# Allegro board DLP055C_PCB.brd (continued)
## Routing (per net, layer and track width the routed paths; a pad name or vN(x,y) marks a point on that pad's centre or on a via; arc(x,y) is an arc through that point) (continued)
UART0_TXD_CON: length 20.6
  TOP w0.191: U46.7 18.82,33.36 16.63,33.36 15.67,32.39 15.67,29.22 14.7,28.25 9.78,28.25 9.37,28.66 J102.2
UART0_VP: length 2.8
  TOP w0.191: U46.2 21.51,30.12 C692.1
UART1_CTSZ: length 92.6
  TOP w0.191: U15.R1 150.95,73.51 150.97,73.48 150.97,73.2 150.97,72.91 149.7,71.64 149.5,71.64 149.12,71.27 149.12,71.22 149.09,71.18 149.09,68.01 149.01,67.93 149.01,67.91 146.14,65.05 146.14,61.2 146.13,61.19 146.13,60.73 146.14,60.72 146.14,58.89 150.36,54.67 150.57,54.67 152.8,52.43 152.8,49.16 153.46,48.5 167.59,48.5 168.93,47.15 168.93,43.95 v1(169.44,43.44)
  LY5 w0.122: v1(169.44,43.44) 172.11,40.78 172.11,28.05 169.41,25.36 167.94,25.36 167.33,24.75 J105.2
  LY12 w0.122: J105.2 167.33,21.32 169.23,19.42 169.23,13.4 170.68,11.95 170.68,9.08 169.46,7.86
UART1_RTSZ: length 92.9
  TOP w0.102: 150.29,73.34 150.29,73.48 150.36,73.56 150.36,75.17 150.6,75.4 U15.R2
  TOP w0.191: v1(144.24,62.57) 145.04,63.37 145.04,64.92 148.32,68.2 148.32,68.21 148.4,68.29 148.4,71.41 148.37,71.44 148.38,71.45 148.44,71.51 148.44,71.55 149.21,72.33 149.42,72.33 150.29,73.2 150.29,73.34
  LY3 w0.122: 161.34,23.1 161.34,24.06 161.03,24.37 161.03,30.59 159.94,31.68 159.94,39.96 159.51,40.39 156.08,40.39 152.95,37.27 149.09,37.27 148.56,37.8 148.56,38.85 v1(148.54,38.87)
  LY12 w0.122: J113.5 163.24,14.08 163.24,18.17 161.34,20.07 161.34,23.1 ; v1(144.24,62.57) 144.1,62.57 141.12,59.59 141.12,57.06 141.42,56.75 141.42,53.14 141.11,52.83 141.11,52.66 141.09,52.64 141.09,48.96 141.11,48.94 141.11,43.7 142.98,41.84 142.98,41.13 143.6,40.51 145.77,40.51 146.45,39.84 147.57,39.84 v1(148.54,38.87)
UART1_RXD: length 96
  TOP w0.102: 150.63,73.34 150.63,74.18 150.57,74.24 150.57,74.56 150.82,74.81 151.28,74.81 151.43,74.96 151.43,75.8 151.95,76.32 U15.T3
  TOP w0.191: 150.63,73.34 150.63,73.05 149.56,71.98 149.36,71.98 148.78,71.41 148.78,71.36 148.74,71.32 148.74,68.15 148.66,68.07 148.66,68.06 145.39,64.78 v1(145.39,62.62)
  LY3 w0.122: v1(149.58,38.06) 152.9,38.06 155.6,40.75 159.97,40.75 160.6,40.12 160.6,31.89 161.44,31.05 161.44,24.49 J105.5
  LY12 w0.122: J105.5 165.07,20.86 165.07,14.03 167.38,11.72 168.14,11.72 J113.3 ; v1(145.39,62.62) 143.51,60.74 142.67,60.74 141.4,59.47 141.4,57.17 141.7,56.87 141.7,53.02 141.39,52.71 141.39,52.55 141.37,52.53 141.37,49.08 141.39,49.06 141.39,44.11 143.25,42.25 143.25,41.24 143.71,40.79 145.89,40.79 146.56,40.12 148.48,40.12 149.58,39.02 v1(149.58,38.06)
UART1_TXD: length 106.6
  TOP w0.191: U15.T4 v1(151.45,77.9)
  LY3 w0.122: v1(153.74,39.99) 154.86,41.11 160.27,41.11 161.08,40.29 161.08,31.96 161.79,31.25 161.79,25.64 J105.4
  LY12 w0.122: J105.4 166.24,25 169.64,25 171.95,22.69 171.95,17.87 169.82,15.73 169.82,13.83 171.04,12.61 172.74,12.61 173.58,11.77 173.58,9.41 172.03,7.86 172,7.86 ; v1(153.74,39.99) 152.37,41.36 151.91,41.36 151.68,41.59 151.68,45.09 150.34,46.44 148.87,46.44 147.42,47.89 144.38,47.89 142.76,49.51 142.76,49.63 142.74,49.65 142.74,51.96 142.76,51.98 142.76,52.1 143.25,52.6 143.25,55.73 145.54,58.02 145.54,58.75 145.54,58.75 145.54,58.79 145.57,58.81 145.57,58.95 147.81,61.2 148.72,61.2 149.05,61.53 149.09,61.53 150.24,62.68 150.24,62.72 150.44,62.92 150.44,64.07 151.33,64.96 151.33,67.27 150.14,68.46 150.14,72.73 150.75,73.34 150.75,74.89 151.96,76.11 151.96,77.35 151.45,77.87 v1(151.45,77.9)
UART2_RXD: length 75.9
  TOP w0.191: J103.5 95.92,137.91 J111.3
  LY12 w0.122: J103.5 95.92,132.44 J98.2
  BOTTOM w0.191: J98.2 96.7,129.68 111.35,129.68 124.05,116.98 124.05,108.57 128.88,103.74 133.12,103.74 134.41,105.04 134.41,106.74 135.43,107.76 139.46,107.76 R615.1
UART2_TXD: length 160.4
  TOP w0.191: v1(171.98,107.99) 170.23,109.74 167.14,109.74 163.75,113.13 160.47,113.13 158.36,115.24 158.36,120.47 155.96,122.87 152.58,122.87 146.56,116.85 146.56,114.7 145.61,113.75 144.17,113.75 143.3,112.88 140.97,112.88 140.65,112.57 v1(140.65,111.82) R614.1 ; J103.4 97.42,144.42 95.78,146.06 92.4,146.06 J111.2
  LY12 w0.122: v1(171.98,107.99) 175.69,104.28 175.69,93.43 173.02,90.76 173.02,88.9 172.13,88.01 172.13,85.62 171.73,85.22 171.73,76.11 v1(169.67,74.05)
  BOTTOM w0.191: v1(169.67,74.05) 171.65,72.06 R711.1 ; v1(140.65,111.82) 140.65,112.32 140.65,112.33 140.63,112.33 140.1,112.86 131.58,112.86 128.99,115.45 126.51,115.45 109.5,132.46 109.5,132.5 109.32,132.67 104.06,132.67 103.07,133.66 99.65,133.66 J103.4
USB_AUX: length 1.8
  TOP w0.191: U7.10 86.46,127.54 v1(85.97,128.04)
  BOTTOM w0.191: v1(85.97,128.04) 85.97,127.87 R91.1
USB_DAT_N: length 80.4
  TOP w0.152: v1(81.79,139.55) 82.08,139.84 82.08,140.13 R4.1
  TOP w0.191: U15.A27 v1(136.45,100.9)
  LY3 w0.076: 136.86,101.31 136.86,102.13 136.68,102.31 136.07,102.31 136.04,102.29 135.93,102.29
  LY3 w0.102: 135.93,102.29 135.9,102.26 135.88,102.26 ; v1(136.45,100.9) 136.86,101.31
  LY3 w0.127: 135.88,102.26 135.52,102.26 135.13,102.66 134.94,102.66 134.93,102.65
  LY3 w0.132: 134.93,102.65 131.53,102.65 127.4,106.78 113.99,106.78 105.94,114.84 101.58,114.84 101.58,114.84 101.47,114.84 94.94,121.37 88.81,121.37 82.09,128.09 82.09,139.25 v1(81.79,139.55)
USB_DAT_N_IN: length 6.3
  TOP w0.152: J2.2 81.9,146.39 82.07,146.22 82.07,143.53 U1.5 82.01,142.55 82.01,142.34 81.76,142.09 R4.2
USB_DAT_P: length 80.5
  TOP w0.152: R5.1 82.38,140.13 82.38,139.83 v1(82.66,139.55)
  TOP w0.191: U15.B27 v1(137.45,100.9)
  LY3 w0.076: 135.96,102.49 135.99,102.49 136.75,102.49 137.03,102.2 137.03,101.4 137.05,101.39 137.05,101.24 137.01,101.2 137.01,101.18 137,101.17 137,101
  LY3 w0.102: 137,101 137.1,100.9 v1(137.45,100.9) ; 135.88,102.54 135.9,102.54 135.96,102.49
  LY3 w0.127: 135.88,102.54 135.63,102.54 135.24,102.93 135.05,102.93 134.93,102.93
  LY3 w0.132: v1(82.66,139.55) 82.37,139.25 82.37,128.2 88.92,121.65 95.06,121.65 101.59,115.12 106.05,115.12 114.11,107.06 127.51,107.06 131.64,102.93 134.93,102.93
USB_DAT_P_IN: length 6.5
  TOP w0.152: 82.62,144.01 82.61,144.01 82.38,143.78 82.38,143.31 82.31,143.25 82.31,141.89 R5.2 ; 82.62,144.01 82.38,144.25 82.38,146.22 82.55,146.39 J2.3 ; 82.62,144.01 U1.3
USB_EN: length 6.3
  TOP w0.191: U7.4 87.96,123.99 88.47,123.48 88.47,119.41 R13.1 R14.1
USB_ENUSB: length 1.3
  TOP w0.191: R8.1 88.26,128.39 87.96,128.09 U7.7
USB_FAULTZ: length 8
  TOP w0.191: U7.8 87.46,128.31 v1(87.55,128.4)
  LY12 w0.122: TP9.1 83.96,131.36 86.93,128.4 v1(87.55,128.4)
  BOTTOM w0.191: v1(87.55,128.4) 87.46,128.31 87.46,127.41 R91.2
USB_ID: length 85
  TOP w0.191: J2.4 83.2,145.49 83.85,144.84 TP286.1 ; U15.C27 v1(138.45,100.9)
  LY3 w0.122: v1(138.45,100.9) 138.45,101.57 137.21,102.81 137.21,102.85 136.65,103.41 136.24,103.41 135.68,103.97 131.75,103.97 126.75,108.97 114.76,108.97 107.76,115.97 103.16,115.97 99.08,120.05 99.08,124.7 98.2,125.58 v1(94.7,125.58)
  LY12 w0.122: v1(94.7,125.58) 93.83,126.45 93.83,130.26 90.62,133.46 90.62,138.18 88.03,140.78 88.03,142.05 TP286.1
USB_ILIM: length 1.5
  TOP w0.191: R11.1 89.21,127.41 89.09,127.29 U7.6
USB_OTG_CP_EN: length 97.7
  TOP w0.191: U15.AB26 v1(158.45,99.9) ; R8.2 v1(90.35,128.39) ; R14.2 v1(91.23,119.39)
  LY3 w0.076: 142.99,99.14 142.82,99.31 139.62,99.31 137.17,99.31
  LY3 w0.102: 137.17,99.31 136.72,98.87 135.88,98.87 ; v1(158.45,99.9) 158.45,99.89 157.94,99.38 157.21,99.38 157.01,99.18 157.01,98.67 156.76,98.43 143.13,98.43 142.99,98.57 142.99,99.14
  LY3 w0.122: v1(91.51,106.1) 91.82,105.8 92.33,105.8 98.98,99.15 120.52,99.15 120.9,98.76 123.9,98.76 124.08,98.94 133.78,98.94 134.24,99.4 135.18,99.4 135.72,98.87 135.88,98.87
  LY12 w0.122: v1(91.51,106.1) 91.19,106.43 91.19,119.36 v1(91.23,119.39) 90.06,120.56 90.06,128.1 v1(90.35,128.39)
USB_TXRTUNE: length 2
  TOP w0.191: U15.C26 v1(139.45,98.9)
  BOTTOM w0.191: v1(139.45,98.9) 138.97,99.38 R114.2
USB_VBUS: length 85.8
  TOP w0.191: 85.84,130.89 v1(85.84,130.89) C7.2 86.96,130.89 ; U15.D26 v1(139.45,99.9)
  TOP w0.381: J2.1 81.25,145.83 v1(81.24,145.82)
  LY12 w0.635: v1(81.24,145.82) 85.84,141.22 v1(85.84,139.02)
  BOTTOM w0.381: v1(139.45,99.9) 139.36,99.9 139.08,100.18 134.32,100.18
  BOTTOM w0.635: 134.32,100.18 133.67,99.53 126.79,99.53 120.7,105.62 120.7,117.34 109.83,128.2 101.6,128.2 100.86,128.94 93.59,128.94 93.29,129.25 87.48,129.25 v1(85.84,130.89)
  vias: v1(85.84,138) v1(85.84,136.99) v1(85.84,135.97) v1(85.84,134.95) v1(85.84,133.94) v1(85.84,132.92) v1(85.84,131.91)
USBDM: length 11.8
  TOP w0.152: U562.15 21.74,76.86 21.5,76.62 20.87,76.62 20.7,76.44 20.7,76.08 20.47,75.85 19.58,75.85 19.15,76.29 18.74,76.29 U501.5 18.69,76.34 18,76.34 16.99,77.35 16.71,77.35 15.31,78.75 14.33,78.75 14.07,78.49 14.07,78.28 J83.2
USBDP: length 11.7
  TOP w0.152: J83.3 13.77,78.28 13.77,78.62 14.2,79.05 15.44,79.05 16.84,77.66 17.52,77.66 17.73,77.87 19.01,77.87 19.53,77.35 20.03,77.35 U501.3 20.46,77.34 20.87,76.92 21.37,76.92 21.8,77.36 U562.14
UVLO_PWRDWN_1: length 63.7
  TOP w0.191: R886.1 v1(88.36,94.55)
  LY5 w0.122: v1(88.36,94.55) 87.37,94.55 85.85,96.07 85.85,104.07 78.81,111.11 78.81,114.97 71.9,121.88 71.9,138.72 74.01,140.83 74.01,145.32 v1(75.31,146.62)
  BOTTOM w0.191: v1(75.31,146.62) 76.2,145.72 U520.4
UVLO_PWRDWN_2: length 73.2
  TOP w0.191: R887.1 v1(81.54,88.76)
  LY5 w0.122: v1(81.54,88.76) 81.22,88.76 79.5,90.48 79.5,103.39 77.16,105.72 74.82,105.72 63.55,117 v1(63.55,149.77)
  BOTTOM w0.191: v1(63.55,149.77) 64.13,149.77 64.55,149.35 U568.4
VAD18_PLLMA: length 3.4
  TOP w0.191: U15.AE19 v1(161.45,92.9)
  BOTTOM w0.381: L15.1 C183.1 U15.AE19 v1(161.45,92.9)
VAD18_PLLMB: length 3.1
  TOP w0.191: U15.F14 v1(141.45,86.9)
  BOTTOM w0.381: C227.1 v1(141.45,86.9) L23.1 C225.1
VAD18_VX1: length 11.2
  TOP w0.191: U15.L19 v1(146.45,92.9) ; U15.E18 v1(140.45,91.9)
  LY3 w0.381: v1(146.45,92.9) 144.91,92.9 144.67,93.14 143.6,93.14 143.14,93.6 142.33,93.6 141.37,92.64 141.19,92.64 v1(140.45,91.9)
  BOTTOM w0.381: v1(146.45,92.9) U15.L19 ; C205.1 v1(140.45,91.9) ; v1(140.45,91.9) C204.1 ; v1(140.45,91.9) U15.E18
VAD33_OSCA: length 2.1
  TOP w0.191: U15.Y18 v1(156.45,91.9)
  BOTTOM w0.381: L17.1 v1(156.45,91.9) U15.Y18
VAD33_OSCB: length 2.1
  TOP w0.191: U15.L17 v1(146.45,90.9)
  BOTTOM w0.381: L20.1 v1(146.45,90.9) U15.L17
VAD33_USB: length 8.3
  TOP w0.191: U15.F25 v1(141.45,98.9) ; U15.D27 v1(139.45,100.9) ; U15.E26 v1(140.45,99.9)
  BOTTOM w0.381: C152.2 v1(139.45,100.9) v1(140.45,99.9) U15.E26 v1(141.45,98.9) U15.F25 143.11,97.03 C172.2
VAD115_VX1: length 12.3
  TOP w0.191: U15.F24 v1(141.45,97.9) ; U15.L18 v1(146.45,91.9)
  LY12 w0.381: v1(141.45,97.9) 145.22,94.12 145.22,93.12 v1(146.45,91.9)
  BOTTOM w0.381: v1(146.45,91.9) U15.L18 ; v1(146.45,91.9) C200.1 ; v1(146.45,91.9) L18.1 ; v1(141.45,97.9) C174.1
VBIAS_MON: length 27.8
  TOP w0.191: v1(158.19,69.12) 158,68.93 R235.1 ; TP285.1 179.12,74.6 179.36,74.6 179.37,74.6 179.4,74.6 179.4,74.59 179.83,74.59 179.84,74.6 179.88,74.6 179.88,74.6 J10.47
  LY3 w0.122: v1(158.19,69.12) 158.26,69.2 159.94,69.2 161.69,70.95 162.05,70.95 163.95,72.86 166.06,72.86 167.69,71.23 169.08,71.23 172.23,74.38 177.62,74.38 TP285.1
VUSB: length 10.5
  TOP w0.191: TP77.1 38.07,108.3 38.07,110.27 34.39,113.95 U26.66
VX1_CM_AMOUT0: length 27.8
  TOP w0.191: U15.F19 141.95,92.4 142.19,92.16 v1(142.69,92.16)
  LY3 w0.076: 141.63,87.31 141.62,87.31 141.62,87.31 141.28,87.31 141.27,87.31 140.62,87.31 140.62,87.31 140.28,87.31 140.27,87.31 139.62,87.31 139.62,87.31 139.28,87.31 139.27,87.31 138.62,87.31 138.62,87.31 138.28,87.31 138.27,87.31 137.62,87.31 137.62,87.31 137.28,87.31 137.27,87.31 136.62,87.31 136.62,87.31 136.28,87.31 136.27,87.31 136.08,87.31 135.88,87.51
  LY3 w0.102: v1(142.69,92.16) 142.24,92.16 142.06,91.98 142.06,87.74 141.63,87.31
  LY3 w0.122: TP106.1 122.12,87.11 128.77,87.11 129.17,87.51 135.88,87.51
VX1_CM_AMOUT1: length 28.3
  TOP w0.102: U15.F21 v1(141.45,94.9)
  LY3 w0.076: 139.95,95.1 140.17,95.31 140.2,95.31 141.03,95.31 v1(141.45,94.9)
  LY3 w0.102: 139.95,95.1 139.95,94.66 139.59,94.3 138.24,94.3 137.85,94.69 135.88,94.69
  LY3 w0.122: 135.88,94.69 135.84,94.65 129.39,94.65 128.96,95.08 117.5,95.08 117.03,94.61 TP107.1
VX1_CM_AMOUT2: length 31.4
  TOP w0.102: U15.F22 v1(141.45,95.9)
  LY3 w0.076: v1(141.45,95.9) 141.04,96.3 140.63,96.3 140.62,96.31 140.28,96.31 140.27,96.3 135.98,96.3
  LY3 w0.102: 135.98,96.3 135.88,96.2
  LY3 w0.122: 135.88,96.2 132.91,96.2 131.95,97.16 129.86,97.16 129,96.3 117.87,96.3 117.01,97.16 TP108.1
VX1_CM_AMOUT3: length 25.9
  TOP w0.102: U15.F23 v1(141.45,96.9)
  LY3 w0.076: 137.84,97.31 138.27,97.31 138.28,97.31 138.62,97.31 138.62,97.31 139.27,97.31 139.28,97.31 139.62,97.31 139.62,97.31 140.27,97.31 140.28,97.31 140.62,97.31 140.62,97.31 141.02,97.31 141.43,96.9 v1(141.45,96.9)
  LY3 w0.102: 135.88,97.11 137.64,97.11 137.84,97.31
  LY3 w0.122: v1(125.35,97.27) 125.83,97.75 135.1,97.75 135.73,97.11 135.88,97.11
  LY12 w0.122: v1(125.35,97.27) 125.35,103.54 124.78,104.11 TP109.1
VX1_DATA0_N: length 9.4
  TOP w0.102: U15.D18 139.65,91.4 139.55,91.5 139.55,91.73 139.26,92.02 135.95,92.02 135.9,92.07 135.88,92.07
  TOP w0.127: 135.88,92.07 135.79,92.07 135.48,91.76 135.48,90.42 133.95,88.89 133.56,88.89 C72.1
VX1_DATA0_P: length 9
  TOP w0.102: 135.88,91.73 135.97,91.82 139.17,91.82 139.35,91.65 139.35,91.5 139.24,91.4 U15.C18
  TOP w0.127: C73.1 133.56,88.59 134.08,88.59 135.79,90.3 135.79,91.64 135.88,91.73
VX1_DATA1_N: length 6.6
  TOP w0.102: U15.B19 137.65,92.4 137.55,92.5 137.55,92.73 137.28,93 136.53,93 136.53,92.99 136.44,92.99 136.4,92.99 136.38,92.97 135.98,92.97 135.9,93.05 135.88,93.05
  TOP w0.127: 135.88,93.05 135.62,93.05 134.62,92.05 134.62,91.44 133.97,90.8 133.56,90.8 C67.1
VX1_DATA1_P: length 6.2
  TOP w0.102: 135.88,92.74 136,92.74 136.03,92.77 136.1,92.77 136.46,92.77 136.48,92.79 136.61,92.79 136.62,92.8 137.19,92.8 137.35,92.64 137.35,92.5 137.24,92.4 U15.A19
  TOP w0.127: C68.1 133.56,90.49 134.1,90.49 134.92,91.32 134.92,91.92 135.74,92.74 135.88,92.74
VX1_DATA2_N: length 7.8
  TOP w0.102: 135.88,94.07 136,94.07 136.04,94.03 136.3,94.03 136.46,94.03 136.48,94.01 139.26,94.01 139.55,93.73 139.55,93.5 139.65,93.4 U15.D20
  TOP w0.127: 135.88,94.07 135.5,94.07 134.14,92.7 133.56,92.7 C65.1
VX1_DATA2_P: length 7.5
  TOP w0.102: 135.88,93.76 135.89,93.76 135.9,93.77 135.9,93.78 135.96,93.83 136.38,93.83 136.4,93.81 139.18,93.81 139.35,93.65 139.35,93.5 139.24,93.4 U15.C20
  TOP w0.127: C66.1 133.56,92.4 134.27,92.4 135.63,93.76 135.88,93.76
VX1_DATA3_N: length 5.4
  TOP w0.102: 135.88,95.03 135.9,95.03 135.96,94.97 136.04,94.97 136.4,94.97 136.41,94.98 136.7,94.98 136.71,94.98 137.19,94.98 137.19,94.98 137.3,94.98 137.55,94.73 137.55,94.5 137.65,94.4 U15.B21
  TOP w0.127: 135.88,95.03 135.15,95.03 134.73,94.61 133.56,94.61 C63.1
VX1_DATA3_P: length 5.1
  TOP w0.102: 135.88,94.73 136,94.73 136.05,94.77 136.12,94.77 136.48,94.77 136.49,94.78 136.78,94.78 136.79,94.78 137.11,94.78 137.11,94.78 137.22,94.78 137.35,94.65 137.35,94.5 137.24,94.4 U15.A21
  TOP w0.127: C64.1 133.56,94.3 134.85,94.3 135.28,94.73 135.88,94.73
VX1_DATA4_N: length 7.4
  TOP w0.102: 135.88,96.06 136,96.06 136.04,96.03 136.12,96.03 136.48,96.03 136.5,96.01 139.27,96.01 139.55,95.73 139.55,95.5 139.65,95.4 U15.D22
  TOP w0.127: 135.88,96.06 135.2,96.06 134.75,96.51 133.56,96.51 C61.1
VX1_DATA4_P: length 7.1
  TOP w0.102: U15.C22 139.24,95.4 139.35,95.5 139.35,95.65 139.18,95.81 136.42,95.81 136.4,95.83 135.95,95.83 135.9,95.78 135.9,95.77 135.89,95.76 135.88,95.76
  TOP w0.127: C62.1 133.56,96.21 134.62,96.21 135.07,95.76 135.88,95.76
VX1_DATA5_N: length 5.8
  TOP w0.102: 135.88,97.07 135.9,97.07 135.95,97.02 137.26,97.02 137.55,96.73 137.55,96.5 137.65,96.4 U15.B23
  TOP w0.127: 135.88,97.07 135.48,97.07 134.13,98.42 133.56,98.42 C53.1
VX1_DATA5_P: length 5.5
  TOP w0.102: U15.A23 137.24,96.4 137.35,96.5 137.35,96.65 137.18,96.82 135.95,96.82 135.9,96.77 135.88,96.77
  TOP w0.127: C54.1 133.56,98.11 134.01,98.11 135.36,96.77 135.88,96.77
VX1_DATA6_N: length 9.9
  TOP w0.102: U15.D24 139.65,97.4 139.55,97.5 139.55,97.73 139.26,98.02 138.79,98.02 138.57,98.24 138.57,99.75 138.3,100.02 136.47,100.02 136.45,100.04 136.29,100.04 136.17,100.04 136.17,100.06 136.11,100.12 136.11,100.14 135.93,100.32 135.88,100.32
  TOP w0.127: 135.88,100.32 135.78,100.32 133.87,102.23 133.56,102.23 C49.1
VX1_DATA6_P: length 9.5
  TOP w0.102: U15.C24 139.24,97.4 139.35,97.5 139.35,97.65 139.18,97.82 138.71,97.82 138.36,98.16 138.36,99.66 138.21,99.82 136.39,99.82 136.37,99.84 136.09,99.84 135.97,99.96 135.97,99.98 135.94,100.01 135.88,100.01
  TOP w0.127: C50.1 133.56,101.92 133.74,101.92 135.66,100.01 135.88,100.01
VX1_DATA7_N: length 5.8
  TOP w0.102: U15.B25 137.65,98.4 137.55,98.5 137.55,98.73 137.28,98.99 136.38,98.99 136.37,98.98 135.96,98.98 135.89,99.04 135.88,99.04
  TOP w0.127: 135.88,99.04 135.52,99.04 134.24,100.32 133.56,100.32 C51.1
VX1_DATA7_P: length 5.4
  TOP w0.102: U15.A25 137.24,98.4 137.35,98.5 137.35,98.65 137.2,98.79 136.46,98.79 136.45,98.78 136.29,98.78 136.04,98.78 136,98.74 135.88,98.74
  TOP w0.127: 135.88,98.74 135.4,98.74 134.12,100.02 133.56,100.02 C52.1
VX1_PROJ_ON: length 19.6
  TOP w0.191: J3.22 119.16,142.78 v1(119.16,142.78)
  LY3 w0.122: J68.2 114.21,140.34 114.85,140.98 116.91,140.98 118.33,142.4 118.35,142.4 118.62,142.67 118.62,142.69 118.71,142.77 119.15,142.77 119.16,142.78 v1(119.16,142.78)
WRP_CAMERA_TRIG: length 27.3
  TOP w0.191: J503.3 152.76,55.38 155.57,55.38 156.88,56.69 156.88,58.52 155.29,60.1 155.29,63.74 154.63,64.4 152.82,64.4 151.63,65.59 151.63,66.49 152.27,67.13 152.3,67.13 152.68,67.5 154.08,67.5 154.09,67.51 154.14,67.51 154.97,68.35 154.97,68.63 154.97,68.63 154.97,70.12 155.26,70.41 155.55,70.41 R675.1
N30083522: length 9.9
  TOP w0.191: U15.AC28 v1(159.45,101.9) ; R673.2 163.65,107.43 163.47,107.25 v1(163.47,105.32)
  LY3 w0.122: v1(159.45,101.9) 159.45,101.9 159.99,102.45 161.84,102.45 161.97,102.57 161.97,104.32 162.96,105.32 v1(163.47,105.32)
N30083525: length 10.6
  TOP w0.191: U15.AC26 v1(159.45,99.9)
  BOTTOM w0.191: v1(159.45,99.9) 159.45,99.95 159.91,100.42 162.76,100.42 163.01,100.67 163.01,101.61 163.95,102.55 163.95,104.83 164.15,105.03 R672.2
N30120583: length 1.4
  BOTTOM w0.381: R739.1 v1(79.23,55.43)
N30120605: length 10
  TOP w0.191: C752.1 65.32,46.99 65.32,48.11 65.76,48.55 66.6,48.55 68.6,50.54 68.6,51.88 68.99,52.27 68.99,52.82 69.04,52.87 69.04,53.57 68.88,53.73 U555.21
N30120666: length 5
  TOP w0.191: U555.17 66.88,53.61 66.68,53.4 66.68,52.74 64.58,50.64 C756.2
N30120670: length 4.8
  TOP w0.191: C756.1 66.26,51.45 67.4,52.6 67.4,52.6 67.7,52.89 67.7,52.98 67.69,52.99 67.69,53.31 67.67,53.33 67.67,53.33 67.4,53.6 67.38,53.6 67.38,53.61 U555.18
N30120771: length 18.4
  BOTTOM w1.016: R742.2 74.85,55.28 82.42,47.71 v1(82.42,42.53) v1(83.84,41.11)
N30120877: length 6.3
  TOP w0.191: TP228.1 74.45,58.69 73.25,58.69 73.14,58.8 U555.30
  BOTTOM w0.889: R742.1 74.77,57.57 TP228.1 75.05,59.29 R747.2
N30121099: length 0.9
  TOP w0.203: 72.99,60.31 U555.33
N30121105: length 4.2
  BOTTOM w0.381: v1(79.17,59.67) 79.17,60.69 78.53,61.32 76.63,61.32 R750.2
N30121107: length 9.2
  TOP w0.191: U555.32 v1(74.24,59.81)
  BOTTOM w0.191: R751.2 72.78,59.98 72.8,59.99 74.05,59.99 v1(74.24,59.81) 74.66,60.23 74.66,61.04 R750.1 74.71,63.47 TP230.1
N30121177: length 1.8
  TOP w1.016: R184.2 60.2,66.93 R175.1
N30121238: length 4.3
  TOP w1.016: L516.1 55.04,66.9 R184.1
N30121260: length 4.7
  TOP w0.203: 65.62,65.71 65.88,65.45 U555.46
  TOP w0.381: 65.31,66.01 65.62,65.71
  TOP w0.635: R175.2 64.39,66.93 65.31,66.01
N30121264:
  vias: v1(46.78,67.42) v1(46.91,68.31) v1(47.8,69.33) v1(47.8,68.31)
N30121294: length 3.5
  TOP w0.203: U555.41 v1(68.38,64.91)
  BOTTOM w0.381: R176.2 67.53,65.92 67.53,65.32 67.92,64.94 68.32,64.94 68.35,64.91 v1(68.38,64.91)
N30121371: length 2
  TOP w0.635: R754.1 R756.2
N30121485: length 6.3
  TOP w0.203: 69.88,52.9 U555.23
  TOP w0.381: 70.44,48.52 69.88,49.07 69.88,52.9
N30121519: length 4
  TOP w0.203: 70.66,52.87 70.38,53.15 U555.24
  TOP w0.381: 70.66,52.87 71.09,52.43
  TOP w0.635: 71.5,50.48 TP234.1 71.5,51.55
N30121523: length 2
  TOP w0.381: TP235.1 64.27,69.49 R759.1
N30121878: length 38
  TOP w0.191: v1(45.99,41.99) J515.1 56.06,41.99 v1(56.07,42) 57.42,43.35 DN4.3 58.64,43.38 58.64,45.96 59.94,47.25 62.15,47.25 63.43,48.54 63.43,51.82 63.6,51.99 63.6,54.14 64.07,54.61 U555.13
  BOTTOM w0.191: C767.1 47.15,41.99 v1(45.99,41.99) 46.07,41.91 46.07,38.41 46.33,38.15 C768.1 ; C769.1 v1(56.07,42)
N30121880: length 4.5
  TOP w0.191: v1(61.79,60.2) 62.18,59.81 U555.5
  BOTTOM w0.191: v1(61.79,60.2) 59.07,60.2 R763.1
N30122104: length 30.1
  TOP w0.191: U555.12 63.18,55.39 63.07,55.27 63.07,48.8 62.1,47.84 54.76,47.84 v1(51.48,44.56)
  LY12 w0.122: v1(50.36,37.11) 51.48,38.24 v1(51.48,44.56)
  BOTTOM w0.191: R768.2 v1(50.36,37.11)
N30122184: length 31.1
  TOP w0.191: v1(60.63,44.38) 62.4,46.16 62.4,46.72 63.8,48.12 63.8,51.38 64.39,51.96 64.39,52.44 64.9,52.96 65.19,52.96 65.33,53.1 65.51,53.1 65.88,53.47 U555.15
  LY3 w0.122: v1(60.63,44.38) 56.31,44.38 54.99,43.06 v1(43.86,43.06)
  BOTTOM w0.191: v1(43.86,43.06) 43.86,42.1 R769.2
N30122255: length 25.2
  TOP w0.191: U555.16 66.34,54.57 66.34,53.55 66.33,53.55 66.33,52.99 65.81,52.46 v1(65.4,52.46)
  LY3 w0.122: v1(65.4,52.46) 55.06,52.46 53.77,51.16 53.77,47.99 v1(50.34,44.56)
  BOTTOM w0.191: v1(50.34,44.56) 50.99,43.91 R771.2
N30122286: length 4.1
  TOP w0.191: R772.2 61.07,63.91 62.5,63.91 63.18,63.22 U555.1
N30122298: length 5
  TOP w0.203: D37.2 58.36,57.3 U555.10
N30122348: length 8.4
  TOP w0.635: J516.1 58.74,83.19 59.76,83.19 60.08,83.51 C771.2 61.49,83.29 63.75,83.29 64.2,83.74 L520.2
N30122394: length 7.8
  TOP w0.191: U555.8 61.67,58.3 61.48,58.5 61.46,58.5 61.16,58.79 61.16,58.81 61.05,58.93 60.82,58.93 59.63,60.12 C772.2 R777.1
N30122422: length 19.5
  TOP w0.203: 68.88,66.66 68.88,66.02 68.88,66.02 68.88,65.62 68.88,65.62 68.88,65.13 68.89,65.12 68.89,64.7 68.88,64.69 U555.40
  TOP w0.381: 68.88,66.66 68.88,77.96 68.5,78.34
  TOP w0.635: D40.2 67.25,80.16 L520.1
N30122436: length 3.9
  TOP w0.191: v1(64.51,53.43) 65.1,53.43 65.37,53.69 65.37,54.6 U555.14
  BOTTOM w0.191: v1(64.51,53.43) 65.15,53.43 65.52,53.8 R776.2
N30122458: length 2.2
  BOTTOM w0.191: C767.2 47.34,40.28 47.98,39.65 R773.2
N30122460: length 3.5
  BOTTOM w0.191: R774.2 44.41,36.88 45.8,36.88 46.21,36.47 C768.2
N30122462: length 2.5
  BOTTOM w0.191: R775.2 C769.2
N30122488: length 3.2
  TOP w0.635: L521.1 71.44,68.05 D39.2
N30122494: length 9.1
  TOP w0.635: C770.2 75.31,73.28 L521.2 ; J517.1 76.18,76.67 ; J517.1 73.99,76.67 ; J517.1 75.09,77.77 ; J517.1 75.09,75.58
N30122512: length 1.3
  TOP w0.203: U555.38 69.88,64.79
N30122563: length 6.2
  TOP w0.635: 82.12,75.58 J518.1 ; J518.1 84.31,75.58 ; J518.1 82.12,77.77 ; J518.1 84.31,77.77
N30125467: length 3.2
  TOP w0.191: v1(34.62,50.4) 34.15,50.4 33.93,50.18 U556.28
  BOTTOM w0.191: R778.1 v1(34.62,50.4)
N30125481: length 3
  TOP w0.191: U556.21 29.51,45.92 29.45,45.86 C773.1
N30125519: length 3.9
  TOP w0.191: U556.17 27.51,45.47 26.93,44.89 26.49,44.89 26.2,44.6 26.17,44.6 25.75,44.18 C777.2
N30125523: length 3.2
  TOP w0.191: U556.18 28.01,44.78 27.43,44.2 C777.1
N30125543: length 3.1
  TOP w0.191: v1(34.16,48.73) 34.12,48.68 U556.25
  BOTTOM w0.191: v1(34.16,48.73) 33.79,49.1 R779.2
N30125602: length 3.2
  TOP w0.191: U556.41 29.01,57 v1(28.85,57.17)
  BOTTOM w0.191: v1(28.85,57.17) 29.01,57.33 29.01,58.74 R780.2
N30125636: length 4.4
  TOP w0.191: R781.1 33.18,44.67 32.46,45.39 31.74,45.39 31.3,45.83 30.7,45.83 30.51,46.03 U556.23
N30125638: length 3.6
  TOP w0.191: v1(27.36,57.32) 27.72,57.32 27.97,57.07 27.97,55.92 28.01,55.89 U556.43
  BOTTOM w0.191: R782.2 27.36,58.48 v1(27.36,57.32)
N30125770: length 28.1
  TOP w0.191: DN8.3 v1(34.61,34.18) ; J519.1 24.79,40.87 24.16,41.51 24.08,41.51 23.9,41.68 v1(23.9,42.78) 23.9,45.73 25.16,46.99 U556.13
  LY3 w0.122: v1(33.8,39.81) 29.82,39.81 28.34,41.28 25.4,41.28 v1(23.9,42.78)
  BOTTOM w0.191: v1(34.61,34.18) 33.01,34.18 C781.1 C782.1 C780.1 32.91,38.91 v1(33.8,39.81)
N30125772: length 5
  TOP w0.191: U556.5 22.91,52.19 22.74,52.36 22.64,52.36 22.58,52.41 22.02,52.41 v1(20.98,53.45)
  BOTTOM w0.191: v1(20.98,53.45) 20.46,53.97 R783.1
N30125789: length 10.5
  TOP w0.191: U556.6 22.83,51.69 22.44,52.07 21.3,52.07 v1(20.94,52.43)
  BOTTOM w0.191: R784.1 19.6,55.91 21.61,55.91 22.53,55 22.53,52.82 22.14,52.43 v1(20.94,52.43)
N30125944: length 2.8
  TOP w0.191: U556.12 v1(23.81,47.02)
  BOTTOM w0.191: v1(23.81,47.02) R785.2
N30126008: length 3.9
  TOP w0.191: U556.35 33.89,53.69 v1(35.07,54.87)
  BOTTOM w0.191: R786.2 35.07,55.85 v1(35.07,54.87)
N30126042: length 7.4
  TOP w0.191: v1(25.14,42.6) 24.35,43.39 24.35,44.84 24.77,45.25 25.32,45.25 25.36,45.28 25.91,45.28 26.51,45.88 U556.15
  BOTTOM w0.191: R787.2 25.14,41.54 v1(25.14,42.6)
N30126057: length 3.6
  TOP w0.191: v1(34.7,53.68) 34.2,53.19 U556.34
  BOTTOM w0.191: v1(34.7,53.68) R788.2
N30126109: length 6.4
  TOP w0.191: v1(20.66,57.78) 22.64,55.8 22.64,54.69 23.14,54.19 U556.1
  BOTTOM w0.191: v1(20.66,57.78) R789.2
N30126111: length 3.7
  TOP w0.191: U556.48 25.51,57.06 v1(25.03,57.53)
  BOTTOM w0.191: R790.2 25.03,56.26 v1(25.03,57.53)
N30126115: length 8.8
  TOP w0.381: R791.2 C779.2 18.79,44.13 17.31,42.65 15.43,42.65 L523.1
N30126127: length 4.2
  TOP w0.203: U556.11 21.51,49.18 21.04,48.72 21.04,48.01 R791.1
N30126129: length 9.8
  TOP w0.191: v1(27.2,42.05) 26.13,43.11 25.14,43.11 24.74,43.52 24.74,44.64 25.01,44.91 25.47,44.91 25.5,44.94 26.06,44.94 27.01,45.89 U556.16
  BOTTOM w0.191: R792.2 28.83,42.05 v1(27.2,42.05)
N30126176: length 5.6
  TOP w0.191: U556.36 33.83,54.19 34.11,54.47 34.11,55.36 v1(33.37,56.09)
  BOTTOM w0.191: v1(33.37,56.09) 33.37,58.18 R793.2
N30126180: length 4.6
  TOP w0.635: J520.1 18.56,64.59 ; J520.1 16.37,62.41 ; J520.1 16.37,64.59
N30126190: length 11.3
  TOP w0.203: D41.2 19.32,49.68 U556.10
  TOP w0.381: D41.2 17.95,49.28 17.95,47.98 16.73,46.76 L523.2
N30126261: length 7.3
  TOP w0.191: U556.8 22.79,50.68 22.47,51 v1(21.36,51)
  BOTTOM w0.191: R798.1 C786.2 20.51,50.6 20.92,51 v1(21.36,51)
N30126303: length 4.8
  TOP w0.191: v1(25.12,45.75) 25.68,45.75 26.01,46.08 U556.14
  BOTTOM w0.191: v1(25.12,45.75) 25.52,46.16 R797.2
N30126337: length 6.2
  TOP w0.635: J521.1 26.18,69.39 ; J521.1 23.99,71.58 ; J521.1 23.99,69.39 ; J521.1 26.18,71.58
N30126343: length 3.9
  BOTTOM w0.191: C780.2 31.23,39.7 31.49,39.96 32.61,39.96 32.89,40.24 32.89,41.26 R794.2
N30126345: length 8
  BOTTOM w0.191: R795.2 24.68,35.13 25.52,34.29 C781.2
N30126347: length 3
  BOTTOM w0.191: R796.2 28.6,36.69 29.84,36.69 30.33,36.2 C782.2
N30126390: length 6.2
  TOP w0.445: J522.1 38.88,42.37 ; J522.1 36.69,40.18 ; J522.1 38.88,40.18 ; J522.1 36.69,42.37
N30128088: length 4.4
  TOP w0.191: U557.28 v1(83.88,99.71)
  BOTTOM w0.191: R799.1 83.88,101.08 v1(83.88,99.71)
N30128102: length 3.5
  TOP w0.191: C787.1 77.77,93.83 U557.21
N30128140: length 3.7
  TOP w0.191: U557.17 75.77,95.26 74.65,94.14 74.65,93.38 C791.2
N30128144: length 3.2
  TOP w0.191: U557.18 76.27,95.28 76.27,95.28 76.27,94.86 76.27,94.86 76.27,93.33 C791.1
N30128164: length 4.1
  TOP w0.191: R800.2 83.92,98.99 83.14,98.21 U557.25
N30128223: length 3
  TOP w0.191: U557.41 v1(77.27,106.82)
  BOTTOM w0.191: R801.2 77.82,107.98 77.27,107.43 v1(77.27,106.82)
N30128257: length 5.3
  TOP w0.191: R802.1 82.22,94.22 v1(81.5,94.22) 81.12,94.6 79.5,94.6 78.77,95.33 U557.23
N30128259: length 9.2
  TOP w0.191: R803.2 70.91,105.34 72.46,106.89 73.83,106.89 74.11,107.17 75.03,107.17 75.48,106.71 75.92,106.71 76.27,106.36 U557.43
N30128391: length 32.4
  TOP w0.191: J523.1 74.98,89.77 74.39,90.36 74.39,91.4 73.02,92.77 73.02,93.73 v1(72.51,94.24) 72.51,96.33 72.71,96.52 U557.13
  LY3 w0.122: v1(72.51,94.24) 70.18,94.24 68.63,92.69 68.63,91.58 66.95,89.9 v1(66.95,89.85)
  BOTTOM w0.191: DN12.3 v1(66.95,89.85) ; v1(72.51,94.24) 73.77,92.99 73.77,92.13 74.27,91.63 74.27,90 75.23,89.04 75.23,87.82 C796.1 74.82,87.4 74.82,85.32 C794.1 74.82,84.86 C795.1
N30128393: length 4.6
  TOP w0.191: U557.5 70.79,101.72 70.79,101.71 70.37,101.71 70.37,101.72 69.85,101.72 v1(69.53,102.03)
  BOTTOM w0.191: R804.1 v1(69.53,102.03)
N30128410: length 5.7
  TOP w0.191: v1(69.16,101.22) 70.42,101.22 70.42,101.22 70.84,101.22 70.84,101.22 U557.6
  BOTTOM w0.191: R805.1 67.2,102.71 67.71,102.2 68.28,102.2 69.16,101.32 v1(69.16,101.22)
N30128565: length 4.9
  TOP w0.191: v1(70.78,97.56) 70.78,98.04 70.95,98.21 U557.12
  BOTTOM w0.191: v1(70.78,97.56) 71.44,96.9 R806.2
N30128629: length 3.8
  TOP w0.191: R807.2 84.57,103.04 84.39,103.22 U557.35
N30128663: length 5.2
  TOP w0.191: v1(73.88,94.7) 74.01,94.7 74.77,95.45 U557.15
  BOTTOM w0.191: v1(73.88,94.7) 74.51,94.7 75.88,93.33 R808.2
N30128678: length 5.1
  TOP w0.191: U557.34 83.59,102.72 83.82,102.49 83.82,101.14 83.99,100.97 R809.2
N30128730: length 2.7
  TOP w0.191: U557.1 72.07,104.19 v1(72.53,104.65)
  BOTTOM w0.191: v1(72.53,104.65) 72.53,104.27 72.33,104.06 71.56,104.06 R810.2
N30128732: length 3.8
  TOP w0.191: v1(73,106.18) 73.59,106.18 73.77,106 U557.48
  BOTTOM w0.191: v1(73,106.18) 73.22,106.41 73.22,108.26 R811.2
N30128736: length 9.4
  TOP w0.381: R812.2 C793.2 68.23,92.99 66.38,92.99 64.43,91.03 L527.1
N30128748: length 4.9
  TOP w0.203: U557.11 69.19,98.71 68.69,98.22 68.69,97.56 R812.1
N30128750: length 10.6
  TOP w0.191: v1(77.19,92.85) 76.22,91.88 74.49,91.88 73.66,92.72 73.66,93.72 75.27,95.34 U557.16
  BOTTOM w0.191: R813.2 78.99,92.85 v1(77.19,92.85)
N30128797: length 3.1
  TOP w0.191: U557.36 81.99,103.72 v1(82.41,104.14)
  BOTTOM w0.191: R814.2 v1(82.41,104.14)
N30128801: length 6.2
  TOP w0.635: 69.07,124.28 J524.1 ; J524.1 71.26,122.1 ; J524.1 69.07,122.1 ; J524.1 71.26,124.28
N30128811: length 11.8
  TOP w0.203: U557.10 64.71,99.21 D45.2
  TOP w0.381: D45.2 64.55,97.66 L527.2
N30128841: length 4.3
  TOP w0.203: 75.43,107.44 77.56,107.44 77.77,107.23 77.77,107.03 77.78,107.03 77.78,106.61 77.77,106.6 U557.40
N30128882: length 22.3
  TOP w0.191: U557.8 70.84,100.21 70.84,100.21 70.42,100.21 70.42,100.21 70.22,100.21 69.74,100.69 62.76,100.69 61.74,101.71 58.75,101.71 58.42,102.04 57.32,102.04 55.77,100.49 55.77,99.7 v1(55.77,99.69)
  BOTTOM w0.191: v1(55.77,99.69) C800.2 R819.1
N30128924: length 4.4
  TOP w0.191: v1(73.22,95.31) 74.08,95.31 74.26,95.49 74.26,96.51 U557.14
  BOTTOM w0.191: R818.2 74.41,95.55 74.16,95.31 v1(73.22,95.31)
N30128952: length 7.3
  TOP w0.203: D47.2 78.27,108.64 U557.39
  TOP w0.381: L529.1 77.69,111.4 D47.2
N30128958: length 6.2
  TOP w0.635: 75.42,124.28 J525.1 ; J525.1 77.61,122.1 ; J525.1 75.42,122.1 ; J525.1 77.61,124.28
N30128964: length 2.1
  BOTTOM w0.191: C794.2 R815.2
N30128966: length 2.5
  BOTTOM w0.191: R816.2 71.23,82.55 C795.2
N30128968: length 2.4
  BOTTOM w0.191: C796.2 78.85,87.63 R817.2
N30128978: length 8.3
  TOP w0.203: U557.38 78.77,106.54 78.97,106.75 84.47,106.75 84.67,106.54 D46.2
N30129011: length 6.2
  TOP w0.635: 95.74,111.94 J526.1 ; J526.1 97.93,111.94 ; J526.1 97.93,114.12 ; J526.1 95.74,114.12
N30131580: length 19.8
  TOP w0.635: 51.73,133.92 TP244.1 ; TP244.1 51.73,132.85 ; TP244.1 52.81,133.92 ; TP244.1 52.81,132.85 ; 40.7,132.45 J527.2 ; J527.2 42.49,132.45 ; J527.2 42.49,134.25 ; J527.2 40.7,134.25 ; 43.87,134.25 J528.2 ; J528.2 45.66,134.25 ; J528.2 45.66,132.45 ; J528.2 43.87,132.45
  LY3 w0.381: v1(54.91,135.37) 58.88,135.37 v1(60.01,136.49)
  BOTTOM w0.381: R826.1 v1(60.01,136.49)
N30131609: length 31.3
  TOP w0.191: v1(74.82,142.42) 76.21,142.42 76.37,142.57 U519.1 ; U522.4 v1(66.23,129.26) ; TP246.1 62.68,131.31 U521.9
  LY3 w0.122: v1(66.23,129.26) 63.41,132.08 TP246.1
  LY12 w0.122: v1(74.82,142.42) 70.52,142.42 68.91,140.8 68.91,131.94 v1(66.23,129.26)
N30131654: length 23.9
  TOP w0.191: U519.2 77.81,141.43 77.62,141.24 v1(77.15,141.24)
  LY12 w0.122: v1(71.62,147.2) 72.31,146.52 72.56,146.52 77.15,141.93 v1(77.15,141.24)
  BOTTOM w0.191: R821.2 78.26,141.24 v1(77.15,141.24) U520.2 ; v1(71.62,147.2) 71.29,147.53 69.72,147.53 69.41,147.23 U569.2 69.41,146.06 68.37,145.02 66.24,145.02 65.5,145.75 U568.2
N30131717: length 11
  TOP w0.635: 28.02,138.67 J529.1 ; J529.1 28.02,136.28 ; J529.1 32.94,136.28 ; J529.1 32.94,138.67
N30131761: length 2.4
  TOP w0.191: C801.1 60.56,125.5 U521.1
N30131777: length 5.2
  TOP w0.191: R827.2 62.04,122.36 R820.1 62.25,122.57 62.25,124.04 62.68,124.47 U521.2
N30131888: length 3.4
  TOP w0.191: v1(62.12,129.63) 62.18,129.56 U521.10
  BOTTOM w0.191: R828.1 60.7,128.76 61.77,128.76 62.18,129.18 62.18,129.56 v1(62.12,129.63)
N30131961: length 10
  TOP w0.635: 28.27,142.28 J529.2 ; J529.2 32.69,142.28 ; J529.2 32.69,144.67 ; J529.2 28.27,144.67
N30131963: length 7.5
  TOP w0.635: J529.3 26.97,142.68 ; J529.3 24.59,138.27 ; J529.3 24.59,142.68
N30132461: length 4.6
  BOTTOM w0.635: U523.3 82.28,90.49 82.55,90.22 R831.2
N30132672: length 5.5
  BOTTOM w0.191: U524.1 167.93,137.43 167.93,135.51 169.1,134.34 169.1,133.83 169.58,133.35 R833.1
N30132680: length 5.2
  BOTTOM w0.191: C812.2 168.8,145.39 168.29,144.88 166.87,144.88 166.69,144.7 U524.7
N30132682: length 3.7
  BOTTOM w0.381: U524.6 v1(165.42,144.91) ; C812.1 v1(167.12,148.69)
N30132740: length 8
  TOP w0.381: C813.2 165.02,132.77 v1(164.58,133.21) v1(164.58,134.22) v1(164.58,135.24) 164.58,137.72 166.04,139.18
N30132787: length 9.3
  BOTTOM w0.191: U524.3 165.43,137.45 165.43,136.08 165.27,135.92 164.46,135.92 163.8,135.26 163.19,135.26 161.62,133.69 160.7,133.69 160.36,133.35 C816.2
N30132791: length 12.1
  TOP w0.191: C813.1 166.71,131.95 v1(167.69,131.95)
  BOTTOM w0.191: U524.2 166.69,131.95 C813.1 166.71,131.95 v1(167.69,131.95) 169.79,131.95 170.5,131.24 R108.2
N30132852: length 6.8
  BOTTOM w0.191: U524.4 163.91,137.22 163.53,137.22 163.51,137.2 163.11,137.2 162.63,136.72 162.63,136.05 161.84,135.25 C817.2
N30132884: length 6.8
  TOP w0.191: U527.3 92.24,90.83 93.33,90.83 94.49,91.99 v1(94.49,94.3)
  BOTTOM w0.191: R835.2 v1(94.49,94.3)
N30132918: length 3.2
  TOP w0.191: U525.5 89.5,95.55 v1(91.2,95.55)
  BOTTOM w0.191: C818.2 91.53,95.89 v1(91.2,95.55)
N30132924: length 2.5
  TOP w0.191: v1(87.72,89.8) 87.72,90.32 87.58,90.46 U526.5
  BOTTOM w0.191: v1(87.72,89.8) 87.72,89.71 87.81,89.62 C819.2
N30133027: length 3.9
  BOTTOM w0.191: U528.3 91.25,89.2 92.7,89.2 93.66,90.17 R837.2
N30133077: length 4.1
  BOTTOM w0.191: U59.1 64.56,124.82 64.94,125.21 66.78,125.21 C820.1
N30133183: length 1.8
  BOTTOM w0.191: U59.10 60,124.82 R838.1
N30178636: length 6
  TOP w0.191: VR1.2 127.32,122.76 R872.2 v1(126.02,122.56)
  BOTTOM w0.191: U538.3 126.37,122.91 v1(126.02,122.56)
N30178648: length 6.8
  TOP w0.191: J532.1 v1(133.01,136.24)
  BOTTOM w0.191: R873.1 C832.2 134.86,136.24 v1(133.01,136.24)
N30178650: length 13.9
  TOP w0.191: J532.2 131.76,132.08 TP279.1
  BOTTOM w0.191: TP279.1 130.63,130.95 130.63,129.29 130.04,128.7 R874.1 126.03,128.69 126.03,127.39 125.72,127.08 U538.2
N30178830: length 9.4
  TOP w0.191: VR2.2 v1(94.47,127)
  BOTTOM w0.191: U566.5 97.77,123.8 97.18,124.39 97.18,127.06 97,127.24 96.24,127.24 R876.2 96.14,127.26 95.25,127.26 94.98,127 v1(94.47,127)
N30178842: length 5.5
  TOP w0.191: v1(97.47,120.22) 97.47,121.9 J533.1
  BOTTOM w0.191: v1(97.47,120.22) C834.2 R877.1
N30178844: length 9.6
  TOP w0.191: v1(98.42,123.76) 98.74,123.43 J533.2
  LY3 w0.122: v1(98.42,123.76) 97.99,123.76 97.42,123.19 TP281.1
  BOTTOM w0.191: U566.6 v1(98.42,123.76) 98.4,123.78 98.4,125.24 R878.1
N30179022: length 7.1
  TOP w0.191: VR3.2 132.22,109.81 v1(133.37,109.81) 133.67,109.52 R880.2
  BOTTOM w0.191: U539.3 131.36,110.19 132.46,110.19 132.84,109.81 v1(133.37,109.81)
N30179034: length 4.9
  TOP w0.191: J535.1 v1(130.17,113.01)
  BOTTOM w0.191: v1(130.17,113.01) 128.81,113.01 C836.2 R881.1
N30179036: length 13
  TOP w0.191: v1(129.99,111.82) 128.65,111.82 J535.2 ; TP283.1 131.33,105.84 R882.1
  BOTTOM w0.191: TP283.1 133.04,106.69 133.04,108.95 132.46,109.53 U539.2 130.2,109.53 129.99,109.74 v1(129.99,111.82)

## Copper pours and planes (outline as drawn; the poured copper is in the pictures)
GND on TOP: 158.03,51.77 155,51.77 154.47,51.23 154.47,49.28 154.52,49.23 157.98,49.23 158.28,49.53 158.28,51.51
GND on TOP: 160.9,54.91 160.44,54.46 160.44,51.56 160.29,51.41 159.78,51.41 159.52,51.16 159.52,50.13 159.79,49.87 161.1,49.87 161.1,52.96 161.18,53.04 161.73,53.04 161.79,52.98 161.79,52.27 161.99,52.27 161.99,53.8 162.06,53.87 162.67,53.87 162.67,54.08 162.06,54.08 161.99,54.15 161.99,55.68 161.79,55.68 161.79,54.99 161.73,54.94 161.15,54.94 161.1,54.99 161.1,55.91 161.61,56.41 163.54,56.41 163.61,56.49 163.61,57.18 163.54,57.25 161.25,57.25 160.9,56.9
GND on TOP: 82.79,127.58 85.2,127.58 86.07,126.72 90.13,126.72 90.21,126.64 90.21,120.78 90.08,120.65 88.81,120.65 88.81,123.62 88.35,124.08 88.35,124.89 88.18,125.07 87.21,125.07 87.11,124.97 87.11,123.34 86.91,123.14 86.12,123.14 86.12,123.8 86.25,123.93 86.7,123.93 86.83,124.05 86.83,124.97 86.73,125.07 82.89,125.07 82.61,125.35 82.61,127.41
GND on TOP: 88.76,129.54 90.77,129.54 91,129.77 91,139.04 90.79,139.24 88.81,139.24 88.53,138.96 88.53,129.77
GND on TOP: 90.13,7.06 91.71,7.06 91.73,7.09 91.73,9.19 91.22,9.7 90.49,9.7 90.03,9.25 90.03,7.16
GND on TOP: 168.57,58.24 170.57,58.24 170.9,58.57 170.9,67.23 170.65,67.49 168.59,67.49 168.57,67.46
GND on TOP, BOTTOM: 185.63,33.69 187.24,33.69 187.24,35.44 185.63,35.44 185.43,35.24 185.43,33.89
GND on TOP, BOTTOM: 185.63,40.77 187.24,40.77 187.24,42.52 185.63,42.52 185.43,42.32 185.43,40.97
GND on L2_GND: 66.16,150.33 66.25,150.48 66.12,150.59 66.58,150.59 66.8,150.38 66.89,150.38 67.1,150.59 69.9,150.59 70.03,150.45 70.72,150.45 70.86,150.59 78.99,150.59 78.99,148.99 81.36,148.99 81.36,150.59 83.74,150.59 83.74,148.99 86.11,148.99 86.11,150.59 187.34,150.59 187.34,0.76 0.76,0.76 0.76,17.34 1.14,17.71 1.14,17.89 0.81,18.22 0.76,18.22 0.76,19.69 1.01,19.69 1.01,19.97 1.11,20.07 1.11,20.18 0.76,20.53 0.76,42.38 1.34,42.96 1.34,44.77 0.76,45.35 0.76,150.59 65.78,150.59 66.01,150.36 66.03,150.34 66.06,150.33
GND on LY4_GND: 0.76,17.68 1.13,17.8 0.89,18.1 0.82,18.1 0.76,18.07 0.76,150.58 78.99,150.58 78.99,148.99 81.36,148.99 81.36,150.59 83.74,150.59 83.74,148.99 86.11,148.99 86.11,150.59 187.34,150.59 187.34,0.76 0.76,0.76
GND on LY6_GND: 0.76,0.76 0.76,16.93 1.22,17.39 1.22,17.4 1.32,17.5 1.4,17.92 1.11,18.24 1.11,20.35 0.76,20.71 0.76,42.88 0.8,42.9 0.81,42.94 0.88,43.01 0.78,42.98 0.76,42.99 0.76,44.76 0.9,44.82 0.8,44.93 0.78,44.94 0.76,44.95 0.76,150.59 65.8,150.59 66.06,150.33 66.72,150.33 66.99,150.59 69.89,150.59 70.07,150.4 70.66,150.4 70.66,150.44 70.81,150.59 78.99,150.59 78.99,148.99 81.36,148.99 81.36,150.59 83.74,150.59 83.74,148.99 86.11,148.99 86.11,150.59 187.34,150.59 187.34,0.76
GND on LY9_GND: 0.76,150.59 66.01,150.59 66.15,150.45 66.77,150.45 66.91,150.59 69.97,150.59 70.11,150.45 70.65,150.45 70.79,150.59 78.99,150.59 78.99,148.99 81.36,148.99 81.36,150.59 83.74,150.59 83.74,148.99 86.11,148.99 86.11,150.59 187.34,150.59 187.34,0.76 0.76,0.76 0.76,17.71 0.99,17.94 0.99,19.98 0.76,20.2 0.76,42.88 0.91,43.03 0.91,44.84 0.76,44.99
GND on LY11_GND: 0.76,150.58 66.01,150.58 66.14,150.45 66.77,150.45 66.9,150.58 69.95,150.58 70.07,150.45 70.66,150.45 70.79,150.58 78.99,150.58 78.99,148.99 81.36,148.99 81.36,150.59 83.74,150.59 83.74,148.99 86.11,148.99 86.11,150.58 187.34,150.58 187.34,0.76 0.76,0.76 0.76,17.66 1.01,17.91 1.01,19.85 0.99,19.88 0.76,20.1 0.76,42.55 0.99,42.78 0.99,45.02 0.76,45.25
GND on L13_GND: 0.76,150.58 78.99,150.58 78.99,148.99 81.36,148.99 81.36,150.59 83.74,150.59 83.74,148.99 86.11,148.99 86.11,150.59 187.34,150.59 187.34,0.76 0.76,0.76 0.76,17.92 0.94,18.09 0.94,19.88 0.76,20.05 0.76,42.76 0.91,42.91 0.91,44.95 0.76,45.09
P5V on TOP (solid shape): 85.67,34.22 85.67,33.05 85.19,32.57 81.3,32.57 81.3,33.93 82.47,33.93 82.47,33.86 82.48,33.79 82.49,33.72 82.52,33.65 82.55,33.58 82.59,33.52 82.63,33.47 82.68,33.42 82.74,33.37 82.8,33.34 82.86,33.3 82.93,33.28 83,33.27 83.07,33.26 83.14,33.26 83.21,33.27 83.28,33.28 83.35,33.3 83.41,33.34 83.47,33.37 83.53,33.42 83.58,33.47 83.62,33.52 83.66,33.58 83.69,33.65 83.72,33.72 83.73,33.79 83.74,33.86 83.74,33.93 83.73,34 83.72,34.07 83.69,34.14 83.66,34.2 83.62,34.26 83.58,34.32 83.53,34.37 83.47,34.41 83.41,34.45 83.35,34.48 83.28,34.5 83.21,34.52 83.14,34.53 83.07,34.53 83,34.52 82.93,34.5 82.86,34.48 82.8,34.45 82.74,34.41 82.68,34.37 82.63,34.32 82.59,34.26 82.55,34.2 82.52,34.14 82.49,34.07 82.48,34 82.47,33.93 81.3,33.93 81.3,34.68 81.35,34.73 85.16,34.73
P5V on BOTTOM: 93.39,29.45 93.39,17 95.15,15.24 128.08,15.24 128.71,14.61 128.71,13.97 126.68,11.94 126.68,8.38 132.14,2.92 177.99,2.92 179.01,3.94 179.01,4.83 178.24,5.59 177.36,5.59 176.21,4.45 133.29,4.45 129.98,7.75 129.98,12.57 131.51,14.1 131.51,16.38 130.11,17.78 99.47,17.78 96.82,20.43 96.82,32.88 92.38,37.32 84.25,37.32 81.33,34.4 81.33,32.11 82.6,30.84 91.99,30.84
P5V on LY7_PLANE: 94.68,69.22 99.25,69.22 100.01,69.98 100.01,77.72 95.95,81.79 95.95,98.93 134.94,137.92 134.94,142.11 134.56,142.49 131,142.49 92.9,104.39 92.9,70.99
P5V_FP_FE on TOP: 129.81,7.14 131.74,7.14 131.94,7.34 131.94,11.05 131.08,11.91 129.73,11.91 129.3,11.48 129.3,7.65
P5V_VX1_FE on TOP: 130.67,139.01 130.67,143.87 129.78,144.75 128.08,144.75 128.03,144.7 128.03,142.39 127.93,142.29 127.93,139.01
P12V on TOP (solid shape): 68.26,134.37 70.83,134.37 70.83,134.26 72.3,134.26 72.3,133.71 70.83,133.71 70.83,132.99 72.3,132.99 72.3,132.44 70.83,132.44 70.83,131.72 72.3,131.72 72.3,131.17 70.83,131.17 70.83,130.45 72.33,130.45 72.33,129.9 70.82,129.9 70.82,129.79 68.26,129.79 68.26,129.44 67.37,129.44 67.37,134.72 68.26,134.72
P12V on TOP: 70.35,129.92 72.58,129.92 73.39,129.11 73.85,129.11 74.46,129.72 74.46,130.89 74.79,131.22 76.11,131.22 77.69,129.64 80.05,129.64 80.2,129.79 80.2,131.75 78.73,133.22 74.94,133.22 74.05,134.11 74.05,134.62 73.55,135.13 71.77,135.13 70.6,136.3 69.41,136.3 69.41,130.86
P12V on TOP: 156.78,52.37 159.42,52.37 159.88,52.83 159.88,54.51 159.85,54.53 155.77,54.53 155.41,54.18 154.75,54.18 154.47,53.9 154.47,52.07 154.5,52.04 156.45,52.04
P12V on BOTTOM: 66.04,119.74 81.07,119.74 84.01,122.68 84.01,138.56 88.58,143.13 88.58,144.65 89.09,145.16 136.97,145.16 138.87,147.07 144.21,147.07 149.8,141.48 151.45,141.48 154.62,144.65 154.62,147.7 151.83,150.5 88.96,150.5 79.69,141.22 69.28,141.22 63.18,135.13 63.18,129.52 64.81,127.89 64.81,120.98
P12V on BOTTOM: 98.74,24.13 139.38,24.13 141.29,26.04 141.29,40 141.92,40.64 141.92,50.8 144.59,53.47 144.59,54.1 145.1,54.61 146.62,54.61 146.75,54.48 146.75,53.72 154.37,53.72 155.13,52.96 158.81,52.96 159.7,53.85 159.7,56.52 158.94,57.28 144.97,57.28 141.8,54.1 136.46,54.1 134.81,52.45 134.81,40.89 134.18,40.26 134.18,30.48 132.4,28.7 98.87,28.7 98.23,28.07 98.23,24.64
P12V on LY7_PLANE: 172.28,130.56 178.63,130.56 185.1,137.03 185.1,144.62 180.12,149.61 149.42,149.61 148.13,148.32 148.13,133.84 154.99,126.98 154.99,118.73 167.18,106.54 167.18,61.07 163.37,57.26 145.59,57.26 144.45,56.12 144.45,53.7 145.33,52.82 163.75,52.82 173.66,62.72 173.66,110.47 162.61,121.52 162.61,135.49 164.78,137.67 170.37,137.67 171.26,136.78 171.26,131.57
P12V_DLPA100 on BOTTOM: 26.97,27.67 59.48,27.67 74.98,43.16 74.98,53.32 73.96,54.34 73.96,56.63 74.34,57.01 75.36,57.01 76.12,56.24 76.12,55.99 77.77,54.34 82.09,54.34 82.72,54.97 82.72,89.75 89.2,96.22 89.2,102.09 87.8,103.49 82.98,103.49 80.06,106.41 80.06,112.12 73.45,118.73 64.98,118.73 62.67,121.03 62.67,121.82 60.52,121.82 60.13,122.2 60.13,125.4 60.36,125.63 62.65,125.63 62.67,125.65 62.67,132.07 60.96,133.79 50.16,133.79 46.29,129.92 46.29,74.68 39.21,67.6 27.33,67.6 16.95,57.23 16.95,37.69
P12V_VIN on TOP: 64.05,119.21 65.76,119.21 65.96,119.01 67.2,119.01 67.53,119.34 67.53,120.66 64.54,123.66 64.54,125.46 64.16,125.84 63.22,125.84 63.04,125.66 63.04,124.47 63.55,123.96 63.55,121.01 62.28,119.74 57.96,119.74 56.94,120.76 56.94,126.48 55.8,127.62 55.8,130.29 55.55,130.54 54.66,130.54 54.4,130.29 54.4,128 53.77,127.36 49.96,127.36 45.64,131.68 40.43,131.68 40.05,131.3 40.05,128.25 40.56,127.75 44.5,127.75 54.15,118.09 62.94,118.09
P12V_VIN on LY8_PLANE: 71.47,116.16 75.99,120.68 91.11,120.68 100.2,111.59 116.91,111.59 119.66,114.33 119.66,120.48 122.55,123.38 133.9,123.38 138.17,127.64 142.9,127.64 143.1,127.85 169.62,127.85 173.07,131.3 173.07,144.87 172.67,145.27 169.26,145.27 165.65,141.66 165.65,133.66 163.45,131.45 140.51,131.45 139.85,132.11 129.38,132.11 128.57,131.3 110.08,131.3 106.14,127.36 106.14,119.47 104.9,118.22 103.65,118.22 91.84,130.03 63.95,130.03 59.51,134.48 48.08,134.48 45.69,132.09 40.71,132.09 39.75,131.12 39.75,129.32 41.09,127.97 45.28,127.97 57.1,116.16
VDD33_FPD on LY7_PLANE: 139.13,78.36 142.81,78.36 143.07,78.61 143.07,79.1 147.24,83.28 147.24,85.58 146.73,86.09 142.32,86.09 141.03,87.38 138.87,87.38 138.87,78.61
(no net) on TOP: 66.15,64.69 66.26,64.58 66.26,63.05 66.37,62.95 66.44,62.95 66.49,63 66.49,66.71 64.26,68.94 63.83,68.94 63.83,68 64.18,68 66.15,66.04
(no net) on TOP: 68.97,75.79 68.97,78.61 68.29,79.3 68.29,85.78 67.86,86.21 67.17,86.21 66.56,85.6 66.56,82.22 65.93,81.58 65.93,78.82 66.59,78.16 68.03,78.16 68.8,77.39 68.8,75.77 68.87,75.69
(no net) on TOP: 67.73,44.85 67.73,43.18 61.59,37.04 61.59,35.8 66.35,35.8 70.07,39.52 70.07,45.57 70.66,46.15 70.66,48.85 70.62,48.89 70.62,49.83 69.95,50.5 69.64,50.5 69.64,48.98 69.69,48.93 69.69,46.62 68.74,45.66 68.54,45.66
(no net) on TOP: 81.3,32.57 85.19,32.57 85.67,33.05 85.67,34.22 85.16,34.73 81.35,34.73 81.3,34.68
(no net) on TOP: 51.74,72.48 56.18,68.03 62.94,68.03 62.94,68.97 62.3,68.97 61.51,69.76 57.12,69.76 54.66,72.22 54.66,76.59 53.39,77.86 53.39,78.6 53.34,78.65 52.37,78.65 52.37,77.94 51.74,77.3
(no net) on TOP: 70.35,53.37 70.35,50.99 71.29,50.06 71.29,46.25 70.9,45.86 70.9,45.2 71.21,44.9 71.87,44.9 72.28,45.31 72.28,51.44
(no net) on TOP: 77.92,59.95 79.52,59.95 82.93,56.55 82.93,54.57 82.7,54.34 81.43,54.34 78.25,57.51 77.01,57.51 77.01,59.04
(no net) on TOP: 71.97,57.71 73.02,57.71 73.09,57.64 73.73,57.64 75.29,56.08 76.69,56.08 81.8,50.97 81.8,47.9 82.5,47.2 87.88,47.2 87.88,51.27 85.37,53.78 81.26,53.78 78,57.03 76.81,57.03 76.63,57.21 76.63,57.83 76.2,58.26 73.29,58.26 72.94,57.91 71.92,57.91 71.89,57.89 71.89,57.78
(no net) on TOP: 84.89,78.33 82.33,78.33 81.69,77.69 81.69,75.66 79.66,73.63 78.34,73.63 78.11,73.4 78.11,71.72 78.54,71.29 79.86,71.29 80.37,71.8 83.95,71.8 85.17,73.02 85.17,78.05
(no net) on TOP: 77.89,34.72 80.45,34.72 80.66,34.52 80.66,32.97 80.23,32.54 78.83,32.54 77.64,33.73 77.64,34.47
(no net) on TOP: 70.88,43.55 70.88,38.14 76.01,33.01 76.8,33.01 77,33.22 77,37.15 72.5,41.65 72.5,43.38 71.95,43.93 71.26,43.93
(no net) on TOP: 62.04,75.02 62.04,72.86 66.28,68.62 66.28,67.25 67.26,66.28 67.26,63.15 67.38,63.03 67.46,63.1 67.46,64.65 67.74,64.93 67.74,67.79 67.83,67.89 67.83,69.61 67.17,70.27 66.18,70.27 64.83,71.62 64.83,74.77 64.5,75.1 62.12,75.1
(no net) on TOP: 71.36,56.29 71.36,54.99 72.61,53.75 72.61,51.16 73.46,50.3 74.14,50.3 76.35,48.09 76.35,40.12 77.06,39.4 78.13,39.4 78.84,40.12 78.84,49.54 77.87,50.5 77.07,50.5 76.61,50.96 76.07,50.96 76,51.03 76,51.57 72.66,54.91 72.66,56.39 71.46,56.39
(no net) on TOP: 71.74,60.2 75.91,60.2 75.99,60.28 77.75,60.28 79.8,62.34 79.8,63.61 76.63,63.61 73.58,60.56 73.57,60.58 73.06,60.58 72.91,60.43 71.74,60.43
(no net) on TOP: 59.66,54.21 61.77,54.21 61.77,56.27 62.19,56.69 63.67,56.69 63.69,56.72 63.69,56.85 63.61,56.92 61.18,56.92 59.66,55.41
(no net) on TOP: 70.47,72.67 74.43,72.67 74.98,72.12 77.01,72.12 77.01,79.61 72.31,79.61 69.74,77.04 69.74,73.41
(no net) on TOP: 80.1,65.24 80.26,65.4 80.26,66.02 81.71,67.47 83.66,67.47 84.91,68.72 84.91,70.06 82.23,70.06 80.73,68.55 78.57,68.55 77.42,67.41 77.42,67.12 76.42,66.13 70.63,66.13 69.72,65.21 69.72,64.5 69.77,64.45 76.99,64.45 77.78,65.24
(no net) on TOP: 51.86,48.78 53.41,48.78 53.41,52.74 55.24,54.57 58.49,54.57 61.06,57.13 62.21,57.13 62.28,57.2 63.49,57.2 63.49,57.33 63.39,57.43 62.33,57.43 62.2,57.55 60.99,57.55 60.56,57.99 56.98,57.99 56.98,56.34 56.53,55.88 53.73,55.88 51.86,54.01
(no net) on TOP: 71.67,56.72 72.96,56.72 73.27,56.41 73.27,54.99 76.97,51.29 79.14,51.29 79.14,52.76 76.1,55.8 74.43,55.8 73.32,56.92 71.64,56.92 71.62,56.9 71.62,56.77
(no net) on TOP: 56.43,48.77 59.58,48.77 60.68,49.87 60.68,51.75 61.79,52.86 61.79,53.68 58.92,53.68 58.54,54.06 56.43,54.06
(no net) on TOP: 69.48,63.17 69.48,64.42 69.54,64.48 69.54,65.44 70.65,66.55 71.62,66.55 71.92,66.85 71.92,68.12 71.87,68.17 73.04,69.34 73.04,70.71 72.81,70.94 70.29,70.94 69.46,70.1 69.46,66.52 69.18,66.24 69.18,64.52 69.28,64.41 69.28,63.12 69.43,63.12
DMD_P12V on TOP: 172,123.05 179.5,123.05 180.01,123.55 181.53,123.55 181.66,123.68 181.66,126.6 181.15,127.11 169.97,127.11 169.34,127.75 167.94,127.75 167.31,127.11 167.31,126.09 168.07,125.33 169.72,125.33
P1P8V on TOP: 90.98,39.73 91.49,39.73 92.38,40.62 92.38,46.34 93.26,47.23 93.26,52.31 92.25,53.32 88.82,53.32 88.57,53.07 88.57,52.56 89.71,51.42 89.71,43.42 90.98,42.15
P1P8V on BOTTOM: 100.43,83.55 101.1,84.23 101.1,94.18 101.66,94.74 101.7,94.74 107.23,100.28 107.23,108.82 108.38,109.97 111.3,109.97 111.68,109.58 111.68,101.33 123.74,89.26 123.74,79.49 126.41,76.82 129.59,76.82 134.79,71.61 138.3,71.61 138.98,70.93 138.98,68.31 140.31,66.99 144.32,66.99 147.54,70.21 147.54,75.62 146.68,76.49 139.54,76.49 137.84,78.19 137.84,78.6 131.87,84.57 130.35,84.57 128.98,85.94 128.98,91.53 116.51,104 116.51,114.46 113.89,117.08 105.96,117.08 93.9,105.01 93.9,101.5 97.28,98.12 97.29,98.12 98.06,97.36 98.06,88.37 97.29,87.6 84.16,87.6 84.04,87.48 84.04,86.36 88.57,81.83 88.57,49.51 89.58,48.5 89.58,43.54 90.34,42.78 91.49,42.78 92.12,43.42 92.12,46.47 93.14,47.48 93.14,47.99 92.38,48.75 92.38,53.09 94.52,55.24 94.52,77.69 100.38,83.55
